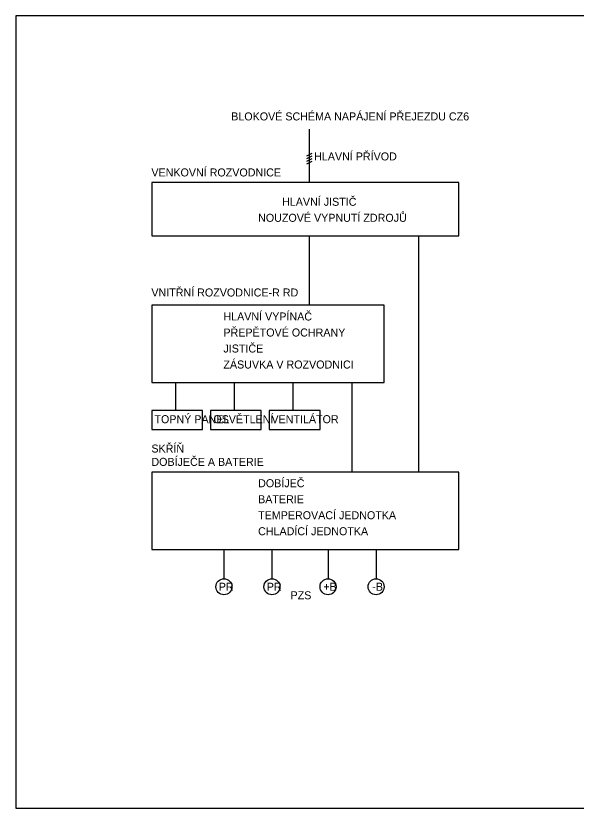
# Model space of a CAD drawing. Extents: x 2343 to 7744, y -6590 to 2050.
# Drawn here: x 5630 to 5840, y -6590 to -6293 of the extents above; entities that cross this region are included whole.
import ezdxf

# ---------------------------------------------------------------- set-up
doc = ezdxf.new("R2010")
doc.units = 0
doc.layers.add('Default', color=7, linetype='Continuous')
doc.layers.add('Vrstva 63', color=7, linetype='Continuous')

msp = doc.modelspace()

# ---------------------------------------------------------------- linework, layer by layer
at = {"layer": 'Default'}
for p, q in [((5740, -6355.5), (5740, -6335.5)), ((5739, -6345.5), (5741, -6344.5)), ((5739, -6346.5), (5741, -6345.5)), ((5739, -6347.5), (5741, -6346.5)), ((5739, -6348.5), (5741, -6347.5)), ((5796, -6355.5), (5681, -6355.5)), ((5681, -6355.5), (5681, -6375.5)), ((5796, -6375.5), (5796, -6355.5)), ((5681, -6375.5), (5796, -6375.5)), ((5740, -6401.5), (5740, -6375.5)), ((5781, -6464), (5781, -6375.5)), ((5768, -6401.5), (5681, -6401.5)), ((5681, -6401.5), (5681, -6430.5)), ((5768, -6430.5), (5768, -6401.5)), ((5681, -6430.5), (5768, -6430.5)), ((5690, -6441), (5690, -6430.5)), ((5712, -6441), (5712, -6430.5)), ((5734, -6441), (5734, -6430.5)), ((5756, -6464), (5756, -6430.5)), ((5700, -6441), (5681, -6441)), ((5681, -6441), (5681, -6448)), ((5700, -6448), (5700, -6441)), ((5722, -6441), (5703, -6441)), ((5703, -6441), (5703, -6448)), ((5722, -6448), (5722, -6441)), ((5744, -6441), (5725, -6441)), ((5725, -6441), (5725, -6448)), ((5744, -6448), (5744, -6441)), ((5681, -6448), (5700, -6448)), ((5703, -6448), (5722, -6448)), ((5725, -6448), (5744, -6448)), ((5796, -6464), (5681, -6464)), ((5681, -6464), (5681, -6493)), ((5796, -6493), (5796, -6464)), ((5681, -6493), (5796, -6493)), ((5708, -6493), (5708, -6504)), ((5726, -6493), (5726, -6504)), ((5747, -6493), (5747, -6504)), ((5765, -6493), (5765, -6504))]:
    msp.add_line(p, q, dxfattribs=at)
for centre in [(5708, -6507), (5726, -6507), (5747, -6507), (5765, -6507)]:
    msp.add_circle(centre, 3, dxfattribs=at)
at = {"layer": 'Vrstva 63'}
msp.add_lwpolyline([(5630, -6590), (6050, -6590), (6050, -6293), (5630, -6293)], close=True, dxfattribs=at)

# ---------------------------------------------------------------- texts
at = {"layer": 'Default'}
for s, p in [('BLOKOVÉ SCHÉMA NAPÁJENÍ PŘEJEZDU CZ6', (5710.72, -6332.2)), ('HLAVNÍ PŘÍVOD', (5741.8, -6347.2)), ('VENKOVNÍ ROZVODNICE', (5680.8, -6353.2)), ('HLAVNÍ JISTIČ', (5729.8, -6364.2)), ('NOUZOVÉ VYPNUTÍ ZDROJŮ', (5720.8, -6370.2)), ('VNITŘNÍ ROZVODNICE-R RD', (5680.8, -6398.2)), ('HLAVNÍ VYPÍNAČ', (5707.8, -6407.2)), ('PŘEPĚTOVÉ OCHRANY', (5707.8, -6413.2)), ('JISTIČE', (5707.8, -6419.2)), ('ZÁSUVKA V ROZVODNICI', (5707.8, -6425.2)), ('TOPNÝ PANEL', (5681.95, -6445.7)), ('OSVĚTLENÍ', (5704.02, -6445.7)), ('VENTILÁTOR', (5725.8, -6445.7)), ('SKŘÍŇ', (5680.8, -6456.7)), ('DOBÍJEČE A BATERIE', (5680.8, -6461.7)), ('DOBÍJEČ', (5720.8, -6469.7)), ('BATERIE', (5720.8, -6475.7)), ('TEMPEROVACÍ JEDNOTKA', (5720.8, -6481.7)), ('CHLADÍCÍ JEDNOTKA', (5720.8, -6487.7)), ('PR', (5706.06, -6508.5)), ('PR', (5724.06, -6508.5)), ('+B', (5745.25, -6508.5)), ('-B', (5763.6, -6508.5)), ('PZS', (5732.95, -6511.7))]:
    msp.add_text(s, height=3, rotation=360, dxfattribs=at).set_placement(p)

doc.saveas('drawing.dxf')
